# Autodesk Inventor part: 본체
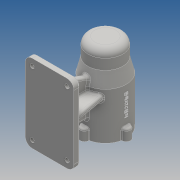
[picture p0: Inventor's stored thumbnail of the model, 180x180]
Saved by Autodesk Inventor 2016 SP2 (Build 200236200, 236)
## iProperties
Created: 2019-07
Part Number: 본체
Material: Generic
Document SubType Name: Modeling
Designer: EZ
Density: 1 g/cm^3
Appearance: Default
Mass: 238.721 g
Surface Area: 654.613 cm^2
Volume: 238.721 cm^3
Author: EZ
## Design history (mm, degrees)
sketch "스케치1"
  geometry: L1 (0, 56)-(0, -56); L2 (24, 10)-(24, -38); L3 (21, -41)-(21, -41); L4 (21, 13)-(21, 13); L5 (21, 24.7)-(21, 13); L6 (21, -41)-(21, -56); L7 (17.5, 42.7)-(17.5, 25); L8 (20.7, 25)-(17.5, 25); L9 (15.7, 47)-(10.5, 47); L10 (7.5, 50)-(0, 50); L11 (16, 46.7)-(16, 43); L12 (17.2, 43)-(16, 43); L13 (10.5, 47)-(10.5, 47); L14 (15, 56)-(0, 56); L15 (30, -56)-(21, -56); L16 (25, 46)-(25, 31); L17 (30, 11)-(25, 31); L18 (30, 11)-(30, -56); A1 r 3 centre (21, -38) between (21, -41) and (24, -38); A2 r 3 centre (21, 10) between (24, 10) and (21, 13); A3 r 0.3 centre (20.7, 24.7) between (21, 24.7) and (20.7, 25); A4 r 0.3 centre (17.2, 42.7) between (17.5, 42.7) and (17.2, 43); A5 r 0.3 centre (15.7, 46.7) between (16, 46.7) and (15.7, 47); A6 r 3 centre (7.5, 47) between (10.5, 47) and (7.5, 50); A7 r 10 centre (15, 46) between (25, 46) and (15, 56); 2 further points
  constraints: 36 end point, 14 point on circle, 14 tangent, 10 parallel, 7 centre point, 4 vertical, 3 equal radius, 3 horizontal, 1 coincident, 1 midpoint, 1 point on line
  dimensions: "d0" = 112 distance of L1.start L1.end; "d3" = 48 diameter of L2 L1; "d5" = 54 distance between parallel lines of L3 L4; "d6" = 42 diameter of L6 L1; "d7" = 42 diameter of L5 L1; "d11" = 35 diameter of L7 L1; "d13" = 3 distance between parallel lines of L9 L10; "d14" = 32 diameter of L11 L1; "d16" = 15 distance between parallel lines of L3 L15; "d17" = 6 distance between parallel lines of L14 L10; "d18" = 3 radius of A1; "d19" = 0.3 radius of A3; "d20" = 3 radius of A6; "d22" = 106 distance between parallel lines of L15 L10; "d23" = 81 distance between parallel lines of L15 L8; "d24" = 99 distance between parallel lines of L15 L12; "d28" = 50 diameter of L16 L1; "d29" = 10 radius of A7; "d30" = 25 distance from line of L16.end L14; "d31" = 45 distance from line of L17.start L14; "d32" = 60 diameter of L18 L1; "d33" = 19.5 distance between parallel lines of L13 L18
revolve "회전1" sketch "스케치1" stored, may be unused: angle "d25" = 90 deg
sketch "스케치2"
  geometry: C1 r 6 at (0, 30); 2 further points
  constraints: 2 vertical alignment, 1 centre point, 1 other
  dimensions: "d34" = 12 diameter of C1
extrude "돌출1" join sketch "스케치2" distance "d35" = 16; taper "d36" = 0 deg
fillet "모깎기1" dims "d37" = 3, "d38" = 1
hole "구멍1" diameter "d44" = 3.242; stored, may be unused: countersink angle "d48" = 90 deg, drill point angle "d50" = 118 deg; dims "d42" = 10, "d43" = 10, "d45" = 8, "d46" = 4, "d47" = 2, "d49" = 11
sketch "스케치3"
  geometry: L1 (-35, -100)-(35, -100); L2 (35, -100)-(35, -110); L3 (35, -110)-(-35, -110); L4 (-35, -110)-(-35, -100); 2 further points
  constraints: 8 end point, 2 parallel, 1 horizontal, 1 midpoint, 1 perpendicular, 1 vertical alignment
  dimensions: "d54" = 70 distance of L2.end L3.end; "d55" = 10 distance of L1.end L2.end; "d56" = 80 distance from line of point (0, -30) L3
extrude "돌출2" join sketch "스케치3" distance "d57" = 112; taper "d58" = 0 deg
sketch "스케치4"
  geometry: L1 (35, -70)-(-35, -70) reference; L2 (-19.654, -22.666)-(-28, -70); L3 (19.654, -22.666)-(28, -70); L4 (-35, -70)-(-35, -80) reference; L5 (35, -80)-(35, -70) reference; A1 r 30 centre (0, 0) between (19.654, -22.666) and (-19.654, -22.666) reference; 1 further point
  constraints: 4 end point, 2 point on circle, 2 point on line
  dimensions: "d59" = 7 distance from line of L4 L2.end; "d60" = 100 deg angle of L1 L2; "d61" = 100 deg angle of L1 L3; "d62" = 7 distance from line of L5 L3.end
extrude "돌출3" join sketch "스케치4" stored distance "d63" = 8; taper "d64" = 0 deg
sketch "스케치5"
  geometry: L1 (-70, -56)-(-70, 56) reference; L2 (-26.663, 20.226)-(-70, 36); L3 (-29, -31)-(-70, -31); L4 (-70, 56)-(-80, 56) reference; L5 (-70, -56)-(-80, -56) reference; L6 (-26.663, 20.226)-(-29, 10.877); L7 (-29, 10.877)-(-29, -31); 2 further points
  constraints: 8 end point, 2 point on line, 1 horizontal, 1 parallel
  dimensions: "d65" = 20 distance from line of L4 L2.end; "d66" = 25 distance from line of L5 L3.end; "d67" = 110 deg angle of L2 L1; "d72" = 1 distance from line of point (-30, 11) L6; "d73" = 1 distance from line of L7 point (-30, 11); "d74" = 75.9638 deg angle of L4 L6
extrude "돌출4" join sketch "스케치5" stored distance "d68" = 8; taper "d69" = 0 deg
fillet "모깎기2" dims "d75" = 10, "d76" = 3
chamfer "모따기1" distance "d77" = 3; stored, may be unused: second distance "d78" = 2, angle "d79" = 45 deg
sketch "스케치6"
  geometry: A1 r 10 centre (50, 99) between (60, 99) and (50, 109) reference; A2 r 10 centre (50, 7) between (50, -3) and (60, 7) reference; A3 r 10 centre (0, 7) between (-10, 7) and (0, -3) reference; A4 r 10 centre (0, 99) between (0, 109) and (-10, 99) reference; 1 further point
hole "구멍2" sketch "스케치6" at (50, 99), (50, 7), (0, 7), (0, 99) diameter "d80" = 6; stored, may be unused: countersink angle "d84" = 90 deg, drill point angle "d86" = 118 deg; dims "d81" = 8, "d82" = 4, "d83" = 2, "d85" = 11
node "작업 평면1"
sketch "스케치7"
  geometry: L1 (2.895, 6)-(2.895, -34); L2 (2.895, -34)-(-2.895, -34); L3 (-2.895, -34)-(-2.895, 6); L4 (-2.895, 6)-(2.895, 6); L5 (30, 11)-(30, -39) reference; L6 (6.771, -56)-(29.226, -56) reference; 2 further points
  constraints: 1 midpoint, 1 parallel, 1 vertical alignment, 2 other
  dimensions: "d88" = 40 distance of L1.start L1.end; "d90" = 22 distance between parallel lines of L6 L2
feature "엠보싱1" sketch "스케치7" dims "d0" = 112, "d3" = 48, "d5" = 54, "d6" = 42, "d7" = 42, "d11" = 35, "d13" = 3, "d14" = 32, "d16" = 15, "d17" = 6, "d18" = 3, "d19" = 0.3, "d20" = 3, "d22" = 106, "d23" = 81, "d24" = 99, "d28" = 50, "d29" = 10, "d30" = 25, "d31" = 45, "d32" = 60, "d33" = 19.5, "d91" = 0.5, "d92" = 0
chamfer "모따기2" distance "d93" = 1; stored, may be unused: second distance "d94" = 2, angle "d95" = 45 deg
node "솔리드1"
pattern_circular "원형 패턴2" dims "d52" = 360 deg
other parameters: "d2" = 42, "d8" = 12, "d9" = 18, "d12" = 4, "d15" = 21, "d21" = 19.5
